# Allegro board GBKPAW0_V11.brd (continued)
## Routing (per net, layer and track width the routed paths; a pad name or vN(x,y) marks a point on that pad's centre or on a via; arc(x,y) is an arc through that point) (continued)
UART2_RXD: length 2.6
  BOTTOM w0.152: R195.2 77.75,12.86 D40.A 76.82,12.9 75.86,13.86 R196.1
UART2_TXD: length 3.5
  BOTTOM w0.152: J9.9 74.21,10.34 74.8,10.34 75.6,11.14 75.6,11.49 R197.1
UART2RXD: length 6.1
  BOTTOM w0.152: J9.10 74.71,8.31 74.71,9.74 75.79,10.83 75.97,10.83 D40.C
UART3_RXD: length 2.3
  BOTTOM w0.152: R199.1 73.51,14.01 D41.A 73.61,12.76 R198.2
UART3_TXD: length 2.8
  BOTTOM w0.152: J9.11 70.9,10.09 R200.1
UART3RXD: length 5.7
  BOTTOM w0.152: D41.C 72.17,10.33 72.17,8.31 J9.12
USB0_DM: length 7.4
  TOP w0.14: R68.1 73.56,26.24 CHK1.3 74.07,26.24 74.29,26.46 75.13,26.46 D20.1 76,26.46 76.52,26.46 77.23,27.17 78.78,27.17 CON2.6
USB0_DP: length 7.9
  TOP w0.14: CON2.7 78.78,27.44 78.25,27.44 78.11,27.58 78.11,27.68 77.97,27.82 77.69,27.82 77.55,27.68 77.55,27.58 77.41,27.44 77.12,27.44 76.41,26.73 76,26.73 D19.1 75.13,26.73 74.01,26.73 CHK1.4 73.69,26.95 R66.1
USB1_DM: length 13.4
  TOP w0.14: CON2.2 81.4,27.17 81.2,27.17 81.06,27.03 81.06,25.61 80.39,24.95 77.37,24.95 76.72,24.3 76.72,22.8 76.31,22.39 75.99,22.39 D22.1 75.13,22.4 74.29,22.4 74.07,22.18 CHK2.3 73.56,22.18 R70.1
USB1_DP: length 13.9
  TOP w0.14: CON2.3 81.4,27.44 81.09,27.44 80.79,27.15 80.79,25.73 80.28,25.22 78.53,25.22 78.39,25.36 78.39,25.44 78.25,25.58 77.97,25.58 77.83,25.44 77.83,25.36 77.69,25.22 77.26,25.22 76.45,24.41 76.45,22.92 76.2,22.66 76,22.66 D21.1 75.13,22.67 74.01,22.67 CHK2.4 73.69,22.89 R69.1
USB_DN: length 18.6
  TOP w0.14: CON3.A7 7.5,26.73 7.61,26.85 7.8,26.85 v1(8.07,26.58) 8.33,26.85 8.88,26.85 9.27,27.23 9.27,28.25 9.68,28.66 9.94,28.66 D18.1 11.02,28.61 12.3,28.61 12.9,29.21 13.1,29.21 13.21,29.11 13.41,29.11 13.6,29.3 13.6,29.5 13.5,29.61 13.5,29.81 13.8,30.11 14.37,30.11 14.51,29.97 14.51,29.74 14.88,29.38 U4.2 ; CON3.B7 5.84,27.73 v1(5.49,27.38)
  BOTTOM w0.14: v1(8.07,26.58) 7.8,26.85 7.12,26.85 6.1,27.87 5.21,27.87 4.83,27.49 4.83,27.26 4.97,27.12 5.23,27.12 v1(5.49,27.38)
USB_DP: length 18.5
  TOP w0.14: U4.1 13.68,30.38 12.19,28.88 11.11,28.88 D16.1 9.94,28.93 9.57,28.93 9,28.36 9,27.34 8.77,27.12 8.33,27.12 v1(8.07,27.38) 7.8,27.12 7.59,27.12 7.48,27.23 CON3.A6 ; CON3.B6 5.84,26.23 v1(5.49,26.58)
  BOTTOM w0.14: v1(5.49,26.58) 5.23,26.85 4.85,26.85 4.56,27.14 4.56,27.6 5.1,28.14 6.21,28.14 7.23,27.12 7.8,27.12 v1(8.07,27.38)
USB_PWR1: length 7.7
  TOP w0.762: CON2.5 78.87,23.8 76.45,21.39 76.45,17.84
USB_VBUS: length 1.5
  TOP w0.381: CON3.A4 v1(8.25,29.43)
  vias: v1(8.31,24.66) v1(8.31,23.8) v1(9.14,31.55) v1(9.14,30.54) v1(9.14,23.8)
USB_VBUSIN: length 4.7
  TOP w0.381: U2.104 58.29,17.97 58.67,17.58 58.67,16.69
N21480035: length 4.1
  TOP w0.254: U7.13 16.77,8.95 16.38,8.56 15.62,8.56 R107.1 R106.1
N21480077: length 2
  TOP w0.254: U7.17 v1(19.04,10.74)
  BOTTOM w0.381: v1(19.04,10.74) 18.17,10.74 C79.1
N21480090: length 6
  TOP w0.254: U7.6 v1(14.5,12.09)
  BOTTOM w0.381: v1(19.55,12.09) 19.33,11.87 14.72,11.87 v1(14.5,12.09)
N21480120: length 2.7
  TOP w0.254: U7.15 v1(19.03,9.69)
  BOTTOM w0.381: v1(19.03,9.69) 18.52,9.69 C80.1
N21480193: length 3.8
  TOP w0.254: R108.1 C36.1 ; C36.1 R109.1 ; C36.1 17.22,8 U7.14
N21480303: length 1.5
  TOP w0.152: D15.A 75.55,30.27 R63.2
N21480386: length 2.6
  BOTTOM w0.381: U9.3 22.63,19.98 22.04,20.57 21.02,20.57 20.95,20.63
N21480402: length 3.7
  BOTTOM w0.381: R168.1 24.26,20.76 ; R168.1 R157.2 ; R168.1 25.12,20.6 U9.4
N21480619: length 3
  TOP w0.381: C36.2 v1(17.14,5.9)
  BOTTOM w0.381: v1(17.14,5.9) 17.02,6.02 R216.1
N21758418: length 4.6
  TOP w0.381: C8.1 74.43,40.57 CON1.1
N21758422: length 5.3
  BOTTOM w0.152: CON1.11 87.5,42.14 87.5,45.14
N21758424: length 3.9
  BOTTOM w0.152: 87.5,46.28 89.1,44.69 CON1.12
N21758431: length 32.3
  TOP w0.152: v1(85.72,48.57) 87.5,50.35 87.5,58.98 86.36,60.13 80.64,60.13 77.85,57.33 75.56,57.33 72.01,53.78 D6.C D5.C
  BOTTOM w0.152: R137.2 v1(85.72,48.57)
N21758441: length 5.9
  BOTTOM w0.152: 87.5,48.57 87.5,52.19 CON1.14
N21758443: length 4.5
  BOTTOM w0.152: CON1.13 89.1,49.02 87.5,47.43
N21788378: length 1.5
  TOP w0.381: U4.10 v1(20.78,31.13)
  BOTTOM w0.381: v1(20.78,31.13) 20.83,31.08 C50.1
N21805568: length 3.1
  TOP w0.381: R51.1 20.29,37.87 J6.1
N21821121: length 2.4
  TOP w0.152: R56.2 22.92,33 U3.2
N21821123: length 2.6
  TOP w0.152: U3.3 22.42,33.65 R54.2
N21821131: length 4
  TOP w0.152: R52.1 R53.2 21.93,34.3 U3.4
N21821540: length 4.8
  TOP w0.152: R62.1 10.16,30.48 10.16,30.28 8.11,28.23 CON3.A5
N21821542: length 4.3
  TOP w0.152: R67.1 9.62,26.82 8.03,25.23 CON3.B5
N21838391: length 9.7
  TOP w0.152: R7.2 11.3,61.52 8.76,61.52 7.11,59.87 7.11,56.82 6.96,56.67 CON5.40
N21838396: length 6
  TOP w0.152: R18.2 8.76,58.73 8.25,58.22 8.25,55.94 7.49,55.17 CON5.37
N21863620: length 1.9
  TOP w0.381: D1.A 21.47,66.1 R1.2
N21889419: length 5.9
  BOTTOM w0.381: C56.1 R153.1 ; C56.1 10.03,26.51 U8.4 ; C56.1 12.35,25.71 Q3.3
N21889500: length 10.2
  BOTTOM w0.254: R159.2 R156.1 14.64,22.28 Q3.1 11.8,21.92 10.77,21.92 R155.1 R165.2 C61.1
N21934934: length 6.6
  BOTTOM w0.381: FB6.1 C45.1 18.14,50.84 17.91,50.6 16.13,50.6 15.66,51.08 SDCARD1.4
N21940880: length 3
  TOP w0.152: R81.2 v1(84.58,17.96)
  BOTTOM w0.152: v1(84.58,17.96) 84.58,17.54 Q5.1
N21942133: length 1.4
  TOP w0.381: R91.1 75.12,12.95 U6.3
N21942139: length 16
  TOP w0.254: R90.2 68.57,13.26 Q2.3 70.29,12.32 77.42,12.32 78.04,12.95 U6.4 79.03,13.01 R92.2 R93.2
N21942279: length 3.8
  TOP w0.152: R82.2 66.93,16.69 69.09,16.69 69.91,15.87 Q2.1
N21952179: length 3.2
  BOTTOM w0.508: FB129.1 19.05,6.72 C81.2 19.92,7.8 J10.2
N21952209: length 7.1
  BOTTOM w0.152: J10.5 25.75,7.63 25.75,9.04 26.25,9.54 27.9,9.54 28.75,10.39 29.01,10.39 R211.2
N21978619: length 1.4
  BOTTOM w0.508: R111.2 6.73,62.41
N22007036: length 3.7
  TOP w0.254: R101.2 49.28,12.63 50.95,14.31 U5.12
N22046592: length 1.8
  BOTTOM w0.152: J5.3 78.36,59.07 D38.C
N22064922: length 7.1
  BOTTOM w0.381: R147.2 23.24,29.39 24.58,28.06 D37.2 24.58,27.16 23.38,25.96 21.08,25.96 20.95,26.09
N22064940: length 8
  BOTTOM w0.381: R221.2 C58.1 25.36,24.57 Q4.1 24.81,24.9 22.05,24.9 20.95,23.8
N22064950: length 7.2
  BOTTOM w0.381: 20.95,24.95 21.44,25.43 23.72,25.43 24.51,26.22 R221.1 25.65,27.02 D37.1
N22064960: length 13.9
  TOP w0.254: v1(23.62,16.44) 21.59,16.44 20.7,15.55 19.3,15.55 R79.1
  BOTTOM w0.381: Q4.3 22.48,23.7 22.48,21.9 R158.2 22.35,21.39 24,19.74 24,16.82 v1(23.62,16.44)
N22065002: length 5.8
  TOP w0.254: Q1.1 18.44,20.15 18.71,20.42 19.52,20.42 19.76,20.17 Q1.3 19.76,18.39 C22.2 21.34,17.96 R73.1
N22065004: length 6.3
  TOP w0.254: R72.1 17.91,16.95 19.3,16.95 19.81,16.44 C22.1 20.83,16.44 R73.2 R74.1
N22065156: length 1.4
  BOTTOM w0.381: R152.1 15.01,26.32 C55.1
N22065188: length 1.6
  TOP w0.254: 18.92,18.09 19.1,18.27 Q1.2
N22065200: length 2.9
  TOP w0.254: Q1.4 20.42,19.38 21.08,18.72 21.97,18.72 R74.2
N218893952: length 2
  BOTTOM w0.381: R148.2 15.56,27.68 U8.3

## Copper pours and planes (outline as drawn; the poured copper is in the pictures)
GND on TOP: 70.74,15.8 73.53,15.8 73.79,15.55 73.79,12.88 73.66,12.76 70.74,12.76 70.48,13.01 70.48,15.55
GND on TOP: 29.34,11.99 33.78,11.99 34.16,11.61 34.16,6.15 33.78,5.77 30.1,5.77 30.1,10.22 29.84,10.47 29.34,10.47 29.08,10.72 29.08,11.74
GND on TOP: 14.99,11.74 15.75,11.74 16,11.99 17.4,11.99 17.53,11.87 17.53,11.49 17.65,11.36 18.29,11.36 18.41,11.23 18.41,11.1 17.78,11.1 17.53,10.85 17.53,10.47 17.4,10.34 16,10.34 15.88,10.47 15.88,10.98 15.75,11.1 15.11,11.1 14.99,11.23
GND on TOP: 89.66,13.14 89.66,15.55 89.15,16.06 89.15,16.69 89.66,17.2 89.66,28.88 89.28,29.27 79.25,29.27 78.99,29.52 78.99,31.04 79.38,31.42 91.82,31.42 92.46,30.79 92.46,13.01 92.33,12.88 89.92,12.88
GND on TOP: 0.76,32.44 0.51,32.69 0.51,61.4 0.63,61.52 6.6,61.52 6.73,61.4 6.73,60.63 6.1,60 6.1,57.59 5.84,57.33 4.7,57.33 4.7,35.11 5.33,34.47 8,34.47 8.25,34.22 13.33,34.22 13.46,34.09 13.46,32.95 12.95,32.44
GND on TOP: 7.37,5.52 6.98,5.9 6.98,9.96 3.56,13.39 3.56,20.25 4.44,21.14 6.35,21.14 6.35,22.79 6.48,22.92 8.64,22.92 8.89,22.66 11.43,22.66 11.81,23.04 11.81,24.19 12.06,24.44 14.48,24.44 14.48,20.63 14.1,20.25 7.49,20.25 6.98,19.74 6.98,16.06 7.37,15.68 12.06,15.68 13.72,14.03 13.72,12.37 14.35,11.74 15.62,11.74 15.62,11.36 14.35,10.09 12.45,10.09 11.81,9.45 11.81,8.06 11.68,7.93 11.05,7.93 10.92,7.8 10.92,5.77 10.67,5.52
GND on TOP: 20.45,15.04 17.91,15.04 17.78,14.91 17.78,13.9 17.91,13.77 18.92,13.77 19.43,14.28 20.32,14.28 20.57,14.53 20.57,14.91
GND on TOP: 76.07,13.64 77.98,13.64 78.1,13.77 78.1,15.68 78.99,16.57 78.99,17.07 79.25,17.33 82.3,17.33 82.55,17.07 82.55,15.42 82.68,15.3 83.57,15.3 83.69,15.42 83.69,18.09 83.57,18.22 77.6,18.22 77.34,17.96 77.34,14.28 77.22,14.15 76.07,14.15
GND on TOP: 83.69,58.86 86.74,58.86 86.99,58.6 86.99,55.55 86.74,55.3 83.57,55.3 83.44,55.43 83.44,58.6
GND on TOP: 22.73,28.88 22.73,30.15 22.99,30.41 24.64,30.41 24.89,30.15 24.89,29.14 24.64,28.88
GND on TOP: 38.35,21.65 42.16,21.65 42.29,21.52 42.29,19.23 42.04,18.98 38.48,18.98 38.23,19.23 38.23,21.52
GND on TOP: 23.88,16.44 23.62,16.69 23.62,17.71 23.88,17.96 28.7,17.96 28.83,18.09 28.83,20.38 28.19,21.01 25.15,21.01 24.89,21.26 24.89,23.17 24.26,23.8 24.26,24.44 24.38,24.57 26.54,24.57 28.96,22.15 29.84,22.15 31.11,20.88 31.11,16.69 30.86,16.44
GND on BOTTOM: 9.02,63.56 9.02,65.08 9.27,65.33 11.43,65.33 11.81,64.95 11.81,64.32 10.67,63.17 9.4,63.17
GND on BOTTOM: 17.02,11.36 17.02,6.28 16.26,5.52 7.37,5.52 7.11,5.77 7.11,9.45 7.37,9.71 12.7,9.71 13.21,9.2 15.62,9.2 15.75,9.33 15.75,11.23 16,11.49 16.89,11.49
GND on BOTTOM: 13.21,29.01 14.99,29.01 15.49,29.52 15.49,30.03 16.76,30.03 16.89,30.15 16.89,30.54 17.02,30.66 19.94,30.66 20.07,30.54 20.07,26.98 19.18,26.09 16.51,26.09 16.38,26.22 16.38,28.12 16.26,28.25 13.33,28.25 13.21,28.38
GND on BOTTOM: 42.04,21.65 35.31,21.65 35.05,21.39 35.05,16.57 35.56,16.06 38.61,16.06 38.86,16.31 38.86,17.2 40.64,18.98 41.91,18.98 42.16,19.23 42.16,21.52
GND on BOTTOM: 3.56,20.76 3.56,18.98 3.94,18.6 9.14,18.6 9.4,18.85 9.4,20.76 9.27,20.88 3.68,20.88
GND on BOTTOM: 0.63,58.22 0.51,58.35 0.51,61.4 0.63,61.52 1.27,61.52 1.9,60.89 6.1,60.89 6.22,60.76 6.22,59.36 5.97,59.11 2.03,59.11 1.14,58.22
GND on BOTTOM: 26.8,19.74 28.32,19.74 30.23,17.84 30.23,16.57 30.1,16.44 28.45,16.44 28.07,16.82 28.07,18.34 27.69,18.72 26.54,18.72 26.54,19.49
GND on BOTTOM: 8.76,28.25 9.78,28.25 10.67,29.14 11.68,29.14 11.94,29.39 11.94,29.65 12.06,29.77 12.83,29.77 12.95,29.65 12.95,26.6 12.83,26.47 12.06,26.47 11.94,26.6 11.94,27.87 11.68,28.12 11.05,28.12 10.16,27.23 8.76,27.23 8.64,27.36 8.64,28.12
GND on BOTTOM: 18.29,15.42 19.94,15.42 21.34,14.03 26.16,14.03 26.54,13.64 26.54,10.6 26.42,10.47 19.94,10.47 19.56,10.85 19.56,12.12 19.18,12.5 18.16,12.5 18.03,12.63 18.03,15.17
GND on BOTTOM: 3.11,24.63 3.11,26.41 3.56,26.85 4.44,26.85 4.76,26.53 4.76,24.5 4.57,24.31 3.43,24.31
GND on BOTTOM: 86.87,57.08 84.96,57.08 83.69,55.81 83.69,55.3 83.82,55.17 86.87,55.17 86.99,55.3 86.99,56.95
GND on BOTTOM: 22.86,18.09 14.73,18.09 13.21,19.61 10.79,19.61 10.67,19.74 10.67,21.52 10.79,21.65 14.1,21.65 15.11,20.63 15.88,20.63 16.51,21.26 17.78,21.26 18.16,21.65 18.16,23.8 18.41,24.06 19.94,24.06 20.19,23.8 20.19,20.38 20.45,20.12 21.34,20.12 21.46,19.99 21.46,19.36 21.97,18.85 22.99,18.85 23.11,18.72 23.11,18.34
GND on BOTTOM: 91.19,36.5 90.17,36.5 89.66,37.01 85.85,37.01 85.6,37.27 85.6,38.92 85.85,39.17 90.93,39.17 91.19,38.92
GND on GND02: 5.08,5.52 0.51,10.09 0.51,63.05 4.95,67.49 87.5,67.49 92.46,62.54 92.46,10.98 86.99,5.52 ; 16 cut-outs
GND_EARTH_L on BOTTOM: 1.14,6.53 0.51,7.17 0.51,22.66 1.14,23.3 2.03,23.3 2.67,22.66 2.67,15.17 6.1,11.74 6.1,7.29 5.33,6.53
GND_EARTH_L on BOTTOM: 0.63,22.53 0.51,22.66 0.51,31.55 0.76,31.81 2.03,31.81 2.29,31.55 2.29,22.66 2.16,22.53
GND_EARTH_R on TOP: 82.17,33.08 81.79,32.69 78.36,32.69 77.98,33.08 77.98,40.31 79.63,41.97 79.63,57.59 80.77,58.73 81.79,58.73 82.17,58.35
GND_EARTH_R on BOTTOM: 78.49,19.49 77.85,20.12 77.85,21.52 78.36,22.03 84.2,22.03 84.8,22.63 84.8,31.84 83.95,32.69 78.1,32.69 77.69,33.11 77.69,40.03 79.63,41.97 79.63,55.94 85.09,61.4 85.09,66.86 85.6,67.37 91.31,67.37 92.46,66.22 92.46,58.86 91.82,58.22 84.71,58.22 82.17,55.68 82.17,37.27 83.95,35.49 92.33,35.49 92.46,35.36 92.46,7.04 90.93,5.52 87.5,5.52 86.87,6.15 86.87,18.85 86.23,19.49
P3V3 on TOP: 65.53,11.87 84.96,11.87 85.22,11.61 85.22,9.2 85.09,9.07 82.93,9.07 81.53,10.47 65.53,10.47 65.41,10.6 65.41,11.74
P3V3 on BOTTOM: 57.91,19.11 57.91,21.52 58.04,21.65 65.28,21.65 65.41,21.77 65.41,55.81 65.66,56.06 67.82,56.06 68.07,55.81 68.07,46.92 66.55,45.39 66.55,21.14 64.26,18.85 58.17,18.85
P3V3 on BOTTOM: 23.49,15.17 20.7,15.17 20.19,15.68 14.73,15.68 14.35,15.3 14.35,12.76 13.97,12.37 10.79,12.37 10.54,12.63 10.54,18.72 11.05,19.23 13.08,19.23 14.48,17.84 23.24,17.84 23.49,17.58
P3V3 on PWR03: 92.46,9.33 91.31,8.18 83.06,8.18 82.93,8.31 82.93,9.96 83.06,10.09 83.44,10.09 84.33,10.98 84.33,14.91 81.66,17.58 78.49,17.58 76.71,19.36 76.71,36.12 65.53,47.3 65.53,55.68 65.41,55.81 31.37,55.81 31.24,55.68 31.24,34.09 30.99,33.84 28.32,33.84 26.54,32.06 17.14,32.06 15.88,33.33 13.59,33.33 13.21,32.95 13.21,29.52 13.97,28.76 13.97,9.83 13.72,9.58 2.41,9.58 0.51,11.48 0.51,62.16 5.71,67.37 86.61,67.37 92.46,61.52 ; 4 cut-outs
P3V3_IN on TOP: 26.04,10.47 25.78,10.72 25.78,16.06 25.91,16.18 31.62,16.18 32,16.57 32,21.39 32.26,21.65 37.59,21.65 37.85,21.39 37.85,13.26 37.47,12.88 28.96,12.88 28.7,12.63 28.7,10.85 28.32,10.47
P3V3_IN on TOP: 17.91,7.17 19.43,7.17 19.56,7.04 19.56,5.77 19.43,5.64 18.03,5.64 17.91,5.77
P3V3_IN on BOTTOM: 27.05,10.72 27.05,14.03 26.67,14.41 24.77,14.41 24.51,14.66 24.51,17.84 24.64,17.96 27.43,17.96 27.56,17.84 27.56,17.07 28.57,16.06 28.57,11.49 27.81,10.72
P3V3_IN on BOTTOM: 18.29,7.93 18.29,6.41 18.54,6.15 19.3,6.15 19.43,6.02 19.43,5.64 19.3,5.52 17.91,5.52 17.78,5.64 17.78,7.93
P5V on TOP: 17.27,12.5 17.27,14.41 17.14,14.53 14.61,14.53 14.48,14.41 14.48,12.63 14.61,12.5
P5V on TOP: 19.81,24.57 23.62,24.57 23.75,24.44 23.75,23.68 24.38,23.04 24.38,21.01 24.77,20.63 28.07,20.63 28.32,20.38 28.32,18.85 28.19,18.72 22.61,18.72 22.23,19.11 21.34,19.11 20.95,19.49 20.95,20.25 20.45,20.76 19.81,20.76 19.56,21.01 19.56,24.31
P5V on TOP: 10.79,37.77 14.99,37.77 15.88,36.89 15.88,31.68 15.62,31.42 13.59,31.42 13.46,31.55 13.46,32.82 13.72,33.08 13.72,34.73 13.59,34.85 11.18,34.85 10.67,35.36 10.67,37.65
P5V on TOP: 78.49,14.66 80.9,14.66 81.15,14.41 81.15,13.9 81.28,13.77 81.91,13.77 82.17,13.52 82.17,13.14 82.3,13.01 83.19,13.01 83.31,13.14 83.31,14.66 83.06,14.91 82.04,14.91 81.79,15.17 81.79,16.95 81.66,17.07 79.63,17.07 79.5,16.95 79.5,15.93 79.38,15.8 78.61,15.8 78.49,15.68
P5V on BOTTOM: 17.14,15.17 14.86,15.17 14.48,14.79 14.48,12.63 14.73,12.37 17.02,12.37 17.14,12.5
P5V on BOTTOM: 13.33,29.39 13.33,29.65 12.7,30.28 12.7,32.69 12.95,32.95 16.38,32.95 17.65,31.68 17.65,31.42 17.53,31.3 17.14,31.3 16.76,30.92 15.49,30.92 15.11,30.54 15.11,29.65 14.86,29.39
P5V on PWR03: 13.72,32.95 15.75,32.95 16.89,31.81 26.92,31.81 28.57,33.46 31.11,33.46 31.37,33.2 31.37,21.77 31.5,21.65 65.28,21.65 65.41,21.77 65.41,44.51 65.66,44.76 67.56,44.76 76.45,35.87 76.45,19.11 78.36,17.2 81.53,17.2 83.95,14.79 83.95,10.98 83.44,10.47 82.93,10.47 82.55,10.09 82.55,6.02 82.04,5.52 11.56,5.52 11.18,5.9 11.18,8.82 11.43,9.07 13.72,9.07 14.35,9.71 14.35,29.01 13.59,29.77 13.59,32.82 ; 2 cut-outs
P5VSB on TOP: 15.24,19.11 17.65,19.11 17.91,19.36 17.91,20.38 18.29,20.76 18.8,20.76 19.18,21.14 19.18,24.44 19.05,24.57 15.49,24.57 15.24,24.31 15.24,21.01 14.99,20.76 14.99,19.36
P5VSB on BOTTOM: 16.64,22.03 17.65,22.03 18.03,22.41 18.03,25.07 17.78,25.33 16.38,25.33 16.26,25.2 16.26,22.41
CH340_P5V on TOP: 12.06,24.57 11.81,24.82 11.81,25.71 11.94,25.84 21.34,25.84 21.59,26.09 21.59,26.6 21.08,27.11 20.57,27.11 20.45,27.23 20.45,27.61 21.08,27.61 21.59,28.12 23.75,28.12 23.88,28 23.88,25.46 23.37,24.95 13.46,24.95 13.08,24.57
CH340_P5V on BOTTOM: 21.08,29.14 22.86,29.14 23.49,28.5 23.49,26.6 23.24,26.34 21.97,26.34 21.72,26.6 20.83,26.6 20.7,26.73 20.7,28.76
USB_PWR1 on TOP: 76.83,14.66 76.83,18.72 76.45,19.11 71.88,19.11 71.63,18.85 71.63,16.44 71.88,16.18 74.04,16.18 75.56,14.66
USB_PWR2 on TOP: 84.33,13.39 84.33,14.91 85.34,15.93 85.34,17.07 87.5,19.23 87.5,22.79 86.99,23.3 81.79,23.3 81.66,23.42 81.66,24.95 81.91,25.2 88.77,25.2 89.28,24.69 89.28,17.45 88.65,16.82 88.65,13.39 88.39,13.14 84.58,13.14
USB_VBUS on TOP: 8.51,31.93 9.52,31.93 9.65,31.81 9.65,30.28 8.38,29.01 6.35,29.01 6.22,29.14 6.22,29.52 6.35,29.65 7.62,29.65 8.38,30.41 8.38,31.81
USB_VBUS on TOP: 6.48,24.82 8.13,24.82 9.14,25.84 10.92,25.84 11.05,25.71 11.05,23.3 10.92,23.17 8.64,23.17 7.62,24.19 6.48,24.19 6.35,24.31 6.35,24.69
USB_VBUS on BOTTOM: 11.68,29.27 7.75,29.27 7.62,29.39 7.62,31.55 7.87,31.81 11.56,31.81 11.68,31.68
USB_VBUS on BOTTOM: 9.78,24.95 6.86,24.95 6.73,24.82 6.73,23.93 7.37,23.3 10.16,23.3 10.29,23.42 10.29,24.44
USB_VBUS on PWR03: 9.52,31.55 9.52,23.8 9.14,23.42 5.97,23.42 4.44,24.95 4.44,28.25 8,31.81 9.27,31.81
N21480090 on TOP: 17.91,12.12 18.54,12.12 19.05,12.63 20.83,12.63 21.21,13.01 21.21,15.55 21.46,15.8 23.75,15.8 24,15.55 24,11.61 23.62,11.23 19.05,11.23 18.67,11.61 17.91,11.61
N21480094 on TOP: 17.53,12.5 18.41,12.5 18.8,12.88 19.3,12.88 19.81,13.39 20.57,13.39 20.7,13.52 20.7,13.9 20.45,14.15 19.56,14.15 18.8,13.39 17.65,13.39 17.53,13.26
N21733684 on TOP: 10.54,14.41 8.38,16.57 7.49,16.57 7.49,19.61 7.75,19.87 13.21,19.87 14.61,18.47 16.38,18.47 16.64,18.22 16.64,15.04 16.38,14.79 14.22,14.79 13.84,14.41
N21838330 on TOP: 5.21,37.77 9.65,37.77 9.91,37.52 9.91,36.63 10.67,35.87 10.67,35.11 10.41,34.85 5.46,34.85 5.21,35.11
N21978619 on BOTTOM: 6.98,61.9 2.79,61.9 1.52,63.17 1.52,65.84 2.03,66.35 4.19,66.35 7.24,63.3 7.24,62.16

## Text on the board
Ref Des/Silkscreen Bottom: RESET | U8 | Q3 | U9 | Q4 | D37 | CLK | MISO | CSN | MOSI | AI3 | AI5 | AI2 | AI6 | AI1 | AI7 | AI0 | AI4 | P5V | GND | LR | MCLK | DI | DO | BCLK | SCL3 | SDA3 | SCL2 | SDA2 | SCL1 | SDA1 | SCL0 | SDA0 | TX3 | RX3 | TX2 | RX2 | TX1 | RX1 | RXCLK | D39 | TXCLK_O | TXCLK_I | P3V3 | Q5 | SDCARD1 | D29 | D41 | D28 | D40 | D38
Board Geometry/Outline: VCUT | CUTOUT
Ref Des/Silkscreen Top: J7 | CON4 | U4 | U7 | U3 | J6 | P5VSB | J10 | L1 | CLK | MISO | MOSI | J1 | P3V3_IN | CSN | GND | 3V3 | PWM0 | PWM1 | PWM2 | J2 | PWM3 | U2 | U5 | RX3 | TX3 | RX2 | J3 | J8 | TX2 | CAN | J9 | D5 | D6 | Q2 | J5 | RX1 | TX | TX1 | RX0 | RX | U6 | TX0 | J4 | LCD | CON5 | CON3 | KEY1 | KEY2 | Q1 | P5V | D1 | D17 | D15 | CON1 | CON2 | GBKPAW0_V11
User.18: FIGURE | SIZE | 10.0 | 20.0 | 32.0 | 35.0 | 36.0 | 39.0 | 40.0 | 43.0 | 47.0 | 67.0 | 90.0 | 105.0 | 24.0 | 128.0 | 68.0x24.0 | 102.0x36.0 | 122.0x36.0 | DRILL CHART: TOP to BOTTOM | ALL UNITS ARE IN MILS | TOLERANCE | +0.0/-0.0 | +2.0/-2.0 | PLATED | NON-PLATED | QTY | 416 | 2 | 6 | 20 | 24 | 40 | 12 | 3 | 4 | 1
